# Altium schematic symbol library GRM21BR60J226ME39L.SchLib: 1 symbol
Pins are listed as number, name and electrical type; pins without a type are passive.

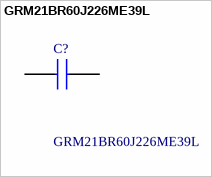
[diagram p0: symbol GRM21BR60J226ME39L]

## GRM21BR60J226ME39L
designator C?
MLCC, 0805; Manufacturer_Name: Murata Electronics; Geometry.Height: 1.45mm
footprint GRM21BR60J226ME39L
pins: 1, 2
